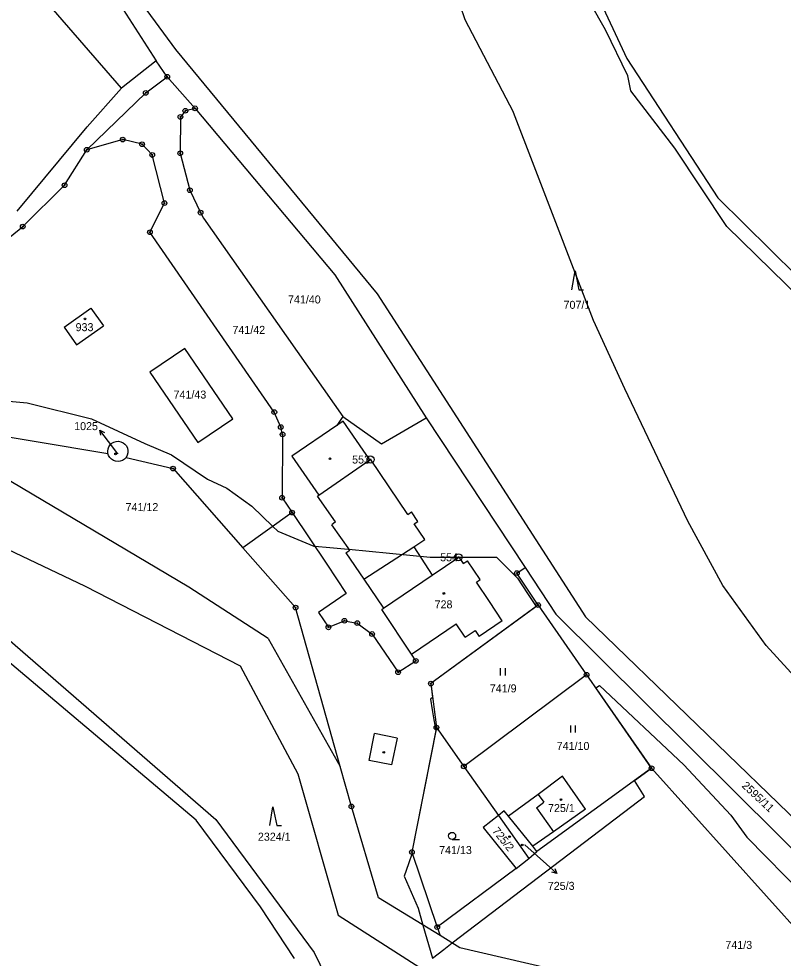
# Model space of a CAD drawing. Extents: x -439246 to -433691, y -1130252 to -1121148.
# Drawn here: x -437300.2 to -437137.8, y -1125272.6 to -1125073 of the extents above; entities that cross this region are included whole.
import ezdxf

# ---------------------------------------------------------------- set-up
doc = ezdxf.new("R2010")
doc.units = 0
for name, color, linetype in [('Vrstva 1', 7, 'Continuous'), ('Vrstva 16', 7, 'Continuous'), ('Vrstva 17', 7, 'Continuous'), ('Vrstva 18', 7, 'Continuous'), ('Vrstva 19', 7, 'Continuous'), ('Vrstva 24', 7, 'Continuous'), ('Vrstva 25', 7, 'Continuous'), ('Vrstva 3', 7, 'Continuous'), ('Vrstva 37', 7, 'Continuous'), ('Vrstva 4', 7, 'Continuous'), ('Vrstva 52', 7, 'Continuous')]:
    doc.layers.add(name, color=color, linetype=linetype)

msp = doc.modelspace()

# ---------------------------------------------------------------- linework, layer by layer
at = {"layer": 'Vrstva 1'}
msp.add_line((-437165.76, -1125232.24), (-437099.03, -1125306.63), dxfattribs=at)
for points in [[(-437184.04, -1125053.49), (-437171.05, -1125081.5)], [(-437281.89, -1125059.16), (-437266.94, -1125079.59)], [(-437278.39, -1125087.76), (-437299.88, -1125062.97)], [(-437278.09, -1125071.06), (-437271.03, -1125081.99)], [(-437266.94, -1125079.59), (-437224.08, -1125131.45)], [(-437271.03, -1125081.99), (-437278.39, -1125087.76)], [(-437268.7, -1125085.36), (-437271.03, -1125081.99)], [(-437171.05, -1125081.5), (-437151.7, -1125111.07)], [(-437273.27, -1125088.78), (-437268.7, -1125085.36)], [(-437268.7, -1125085.36), (-437262.78, -1125092.07)], [(-437285.69, -1125095.97), (-437278.39, -1125087.76)], [(-437285.79, -1125100.86), (-437273.27, -1125088.78)], [(-437262.78, -1125092.07), (-437264.85, -1125092.59)], [(-437262.78, -1125092.07), (-437233.06, -1125127.46)], [(-437265.9, -1125093.89), (-437265.93, -1125101.62)], [(-437264.85, -1125092.59), (-437265.9, -1125093.89)], [(-437300.58, -1125113.93), (-437285.69, -1125095.97)], [(-437278.16, -1125098.71), (-437285.79, -1125100.86)], [(-437274.03, -1125099.7), (-437278.16, -1125098.71)], [(-437271.88, -1125101.98), (-437274.03, -1125099.7)], [(-437290.5, -1125108.4), (-437285.79, -1125100.86)], [(-437269.28, -1125112.21), (-437271.88, -1125101.98)], [(-437265.93, -1125101.62), (-437263.88, -1125109.46)], [(-437299.41, -1125117.2), (-437290.5, -1125108.4)], [(-437263.88, -1125109.46), (-437261.62, -1125114.23)], [(-437272.37, -1125118.4), (-437269.28, -1125112.21)], [(-437151.7, -1125111.07), (-437118.1, -1125144.22)], [(-437261.62, -1125114.23), (-437261, -1125115.42)], [(-437261, -1125115.42), (-437231.4, -1125157.51)], [(-437325.27, -1125138.23), (-437299.41, -1125117.2)], [(-437245.94, -1125156.61), (-437272.37, -1125118.4)], [(-437233.06, -1125127.46), (-437213.7, -1125157.84)], [(-437224.08, -1125131.45), (-437179.84, -1125200.1)], [(-437290.63, -1125138.57), (-437284.92, -1125134.51)], [(-437284.92, -1125134.51), (-437282.26, -1125138.26)], [(-437290.63, -1125138.57), (-437287.96, -1125142.32)], [(-437287.96, -1125142.32), (-437282.26, -1125138.26)], [(-437264.97, -1125143.09), (-437272.43, -1125148.14)], [(-437254.73, -1125158.04), (-437264.97, -1125143.09)], [(-437272.43, -1125148.14), (-437262.19, -1125163.08)], [(-437329.19, -1125157.4), (-437281.29, -1125165.42)], [(-437262.19, -1125163.08), (-437254.73, -1125158.04)], [(-437244.57, -1125159.77), (-437245.94, -1125156.61)], [(-437231.4, -1125157.51), (-437232.69, -1125159.45)], [(-437231.4, -1125157.51), (-437223.14, -1125163.35)], [(-437223.14, -1125163.35), (-437213.7, -1125157.84)], [(-437213.7, -1125157.84), (-437192.64, -1125189.64)], [(-437244.18, -1125161.34), (-437244.57, -1125159.77)], [(-437232.69, -1125159.45), (-437242.19, -1125165.97), (-437236.46, -1125174.27)], [(-437244.18, -1125161.34), (-437244.3, -1125174.79)], [(-437281.27, -1125164.43), (-437281.1, -1125163.96)], [(-437281.1, -1125163.96), (-437280.82, -1125163.54)], [(-437280.82, -1125163.54), (-437280.45, -1125163.21)], [(-437280.45, -1125163.21), (-437280.02, -1125162.96)], [(-437280.02, -1125162.96), (-437279.53, -1125162.83)], [(-437279.53, -1125162.83), (-437279.03, -1125162.8)], [(-437279.03, -1125162.8), (-437278.54, -1125162.9)], [(-437278.54, -1125162.9), (-437278.09, -1125163.1)], [(-437278.09, -1125163.1), (-437277.69, -1125163.4)], [(-437277.69, -1125163.4), (-437277.38, -1125163.79)], [(-437277.38, -1125163.79), (-437277.16, -1125164.24)], [(-437281.35, -1125164.92), (-437281.27, -1125164.43)], [(-437281.29, -1125165.42), (-437281.35, -1125164.92)], [(-437281.16, -1125165.82), (-437281.29, -1125165.42)], [(-437280.9, -1125166.24), (-437281.16, -1125165.82)], [(-437277.18, -1125165.72), (-437277.44, -1125166.21)], [(-437277.06, -1125165.23), (-437277.18, -1125165.72)], [(-437277.16, -1125164.24), (-437277.04, -1125164.73)], [(-437277.04, -1125164.73), (-437277.06, -1125165.23)], [(-437280.56, -1125166.61), (-437280.9, -1125166.24)], [(-437280.13, -1125166.88), (-437280.56, -1125166.61)], [(-437279.66, -1125167.04), (-437280.13, -1125166.88)], [(-437279.16, -1125167.09), (-437279.66, -1125167.04)], [(-437278.67, -1125167.03), (-437279.16, -1125167.09)], [(-437278.2, -1125166.85), (-437278.67, -1125167.03)], [(-437277.78, -1125166.57), (-437278.2, -1125166.85)], [(-437277.44, -1125166.21), (-437277.78, -1125166.57)], [(-437277.44, -1125166.21), (-437267.47, -1125168.61)], [(-437267.47, -1125168.61), (-437252.65, -1125185.42)], [(-437264.1, -1125193.82), (-437301.92, -1125171.31)], [(-437244.3, -1125174.79), (-437242.17, -1125177.95)], [(-437236.76, -1125174.48), (-437236.46, -1125174.27)], [(-437232.96, -1125179.93), (-437236.76, -1125174.48)], [(-437242.17, -1125177.95), (-437252.65, -1125185.42)], [(-437242.17, -1125177.95), (-437234.78, -1125188.87)], [(-437232.96, -1125179.93), (-437233.72, -1125180.52)], [(-437229.93, -1125185.96), (-437233.72, -1125180.52)], [(-437310.14, -1125182.17), (-437286.12, -1125193.55)], [(-437252.65, -1125185.42), (-437241.43, -1125198.13)], [(-437230.72, -1125186.51), (-437229.93, -1125185.96)], [(-437230.72, -1125186.51), (-437226.92, -1125192.08)], [(-437234.78, -1125188.87), (-437230.7, -1125195.16)], [(-437194.39, -1125190.8), (-437192.64, -1125189.64)], [(-437192.64, -1125189.64), (-437186.11, -1125199.49)], [(-437189.89, -1125197.6), (-437194.39, -1125190.8)], [(-437286.12, -1125193.55), (-437253.22, -1125210.53)], [(-437247.25, -1125204.7), (-437264.1, -1125193.82)], [(-437226.92, -1125192.08), (-437222.72, -1125198.23)], [(-437230.7, -1125195.16), (-437236.52, -1125199.18)], [(-437311.33, -1125197.2), (-437258.37, -1125243.11)], [(-437189.89, -1125197.6), (-437212.67, -1125214.28)], [(-437189.89, -1125197.6), (-437179.59, -1125212.39)], [(-437262.54, -1125243.26), (-437315.87, -1125198.3)], [(-437231.95, -1125231.89), (-437241.43, -1125198.13)], [(-437236.52, -1125199.18), (-437234.43, -1125202.32)], [(-437223.12, -1125198.5), (-437222.72, -1125198.23)], [(-437216.77, -1125208), (-437223.12, -1125198.5)], [(-437119.82, -1125265.32), (-437186.11, -1125199.49)], [(-437234.43, -1125202.32), (-437231.04, -1125200.93)], [(-437231.04, -1125200.93), (-437228.31, -1125201.43)], [(-437228.31, -1125201.43), (-437225.15, -1125203.74)], [(-437179.84, -1125200.1), (-437132.38, -1125246)], [(-437225.15, -1125203.74), (-437219.64, -1125211.87)], [(-437247.25, -1125204.7), (-437231.95, -1125231.89)], [(-437215.89, -1125209.44), (-437216.77, -1125208)], [(-437219.64, -1125211.87), (-437215.89, -1125209.44)], [(-437253.22, -1125210.53), (-437240.96, -1125233.42)], [(-437179.59, -1125212.39), (-437205.67, -1125231.86)], [(-437179.59, -1125212.39), (-437165.76, -1125232.24)], [(-437212.67, -1125214.28), (-437211.5, -1125223.61)], [(-437211.5, -1125223.61), (-437216.7, -1125250.05)], [(-437211.5, -1125223.61), (-437205.67, -1125231.86)], [(-437229.57, -1125240.37), (-437231.95, -1125231.89)], [(-437205.67, -1125231.86), (-437198.32, -1125242.27)], [(-437240.96, -1125233.42), (-437232.4, -1125263.46)], [(-437165.76, -1125232.24), (-437190.17, -1125249.92)], [(-437184.68, -1125233.96), (-437189.9, -1125237.8)], [(-437179.78, -1125240.92), (-437184.68, -1125233.96)], [(-437189.9, -1125237.8), (-437196.18, -1125242.41)], [(-437223.78, -1125259.79), (-437229.57, -1125240.37)], [(-437197.08, -1125241.29), (-437198.32, -1125242.27)], [(-437196.18, -1125242.41), (-437197.08, -1125241.29)], [(-437179.78, -1125240.92), (-437186.65, -1125245.76)], [(-437248.91, -1125261.69), (-437262.54, -1125243.26)], [(-437258.37, -1125243.11), (-437237.5, -1125271.39)], [(-437198.32, -1125242.27), (-437201.54, -1125244.81)], [(-437198.32, -1125242.27), (-437191.85, -1125251.43)], [(-437191.04, -1125248.84), (-437196.18, -1125242.41)], [(-437201.54, -1125244.81), (-437194.58, -1125253.52)], [(-437186.65, -1125245.76), (-437191.04, -1125248.84)], [(-437191.85, -1125251.43), (-437190.17, -1125249.92)], [(-437190.17, -1125249.92), (-437191.04, -1125248.84)], [(-437216.7, -1125250.05), (-437211.32, -1125266.01)], [(-437194.58, -1125253.52), (-437191.85, -1125251.43)], [(-437194.58, -1125253.52), (-437211.32, -1125266.01)], [(-437210.71, -1125267.81), (-437223.78, -1125259.79)], [(-437241.63, -1125272.65), (-437248.91, -1125261.69)], [(-437232.4, -1125263.46), (-437207.69, -1125279.24)], [(-437211.32, -1125266.01), (-437210.71, -1125267.81)], [(-437206.51, -1125270.39), (-437210.71, -1125267.81)], [(-437237.5, -1125271.39), (-437232.62, -1125281.42)], [(-437169.29, -1125279.04), (-437206.51, -1125270.39)]]:
    msp.add_lwpolyline(points, dxfattribs=at)
at = {"layer": 'Vrstva 16'}
for p, q in [((-437281.19, -1125162.82), (-437283, -1125160.43)), ((-437188.13, -1125252.6), (-437185.88, -1125254.59))]:
    msp.add_line(p, q, dxfattribs=at)
for points in [[(-437282.8, -1125161.53), (-437283, -1125160.43), (-437282, -1125160.92)], [(-437279.18, -1125165.47), (-437281.19, -1125162.82)], [(-437192.7, -1125248.56), (-437188.13, -1125252.6)], [(-437186.3, -1125253.55), (-437185.88, -1125254.59), (-437186.96, -1125254.3)]]:
    msp.add_lwpolyline(points, dxfattribs=at)
at = {"layer": 'Vrstva 24'}
for centre, radius in [((-437268.7, -1125085.36), 0.5), ((-437268.7, -1125085.36), 0.1), ((-437273.27, -1125088.78), 0.5), ((-437273.27, -1125088.78), 0.1), ((-437264.85, -1125092.59), 0.5), ((-437262.78, -1125092.07), 0.5), ((-437262.78, -1125092.07), 0.1), ((-437265.9, -1125093.89), 0.5), ((-437265.9, -1125093.89), 0.1), ((-437264.85, -1125092.59), 0.1), ((-437278.16, -1125098.71), 0.5), ((-437278.16, -1125098.71), 0.1), ((-437274.03, -1125099.7), 0.5), ((-437274.03, -1125099.7), 0.1), ((-437285.79, -1125100.86), 0.5), ((-437285.79, -1125100.86), 0.1), ((-437271.88, -1125101.98), 0.5), ((-437271.88, -1125101.98), 0.1), ((-437265.93, -1125101.62), 0.5), ((-437265.93, -1125101.62), 0.1), ((-437290.5, -1125108.4), 0.5), ((-437290.5, -1125108.4), 0.1), ((-437263.88, -1125109.46), 0.5), ((-437263.88, -1125109.46), 0.1), ((-437269.28, -1125112.21), 0.5), ((-437269.28, -1125112.21), 0.1), ((-437261.62, -1125114.23), 0.5), ((-437261.62, -1125114.23), 0.1), ((-437299.41, -1125117.2), 0.5), ((-437299.41, -1125117.2), 0.1), ((-437272.37, -1125118.4), 0.5), ((-437272.37, -1125118.4), 0.1), ((-437245.94, -1125156.61), 0.5), ((-437245.94, -1125156.61), 0.1), ((-437244.57, -1125159.77), 0.5), ((-437244.57, -1125159.77), 0.1), ((-437244.18, -1125161.34), 0.5), ((-437244.18, -1125161.34), 0.1), ((-437225.49, -1125166.67), 0.75), ((-437267.47, -1125168.61), 0.5), ((-437225.49, -1125166.67), 0.1), ((-437267.47, -1125168.61), 0.1), ((-437244.3, -1125174.79), 0.5), ((-437244.3, -1125174.79), 0.1), ((-437242.17, -1125177.95), 0.5), ((-437242.17, -1125177.95), 0.1), ((-437206.78, -1125187.44), 0.75), ((-437206.78, -1125187.44), 0.1), ((-437194.39, -1125190.8), 0.5), ((-437194.39, -1125190.8), 0.1), ((-437241.43, -1125198.13), 0.5), ((-437241.43, -1125198.13), 0.1), ((-437189.89, -1125197.6), 0.5), ((-437189.89, -1125197.6), 0.1), ((-437234.43, -1125202.32), 0.5), ((-437231.04, -1125200.93), 0.5), ((-437231.04, -1125200.93), 0.1), ((-437228.31, -1125201.43), 0.5), ((-437228.31, -1125201.43), 0.1), ((-437234.43, -1125202.32), 0.1), ((-437225.15, -1125203.74), 0.5), ((-437225.15, -1125203.74), 0.1), ((-437215.89, -1125209.44), 0.5), ((-437215.89, -1125209.44), 0.1), ((-437219.64, -1125211.87), 0.5), ((-437219.64, -1125211.87), 0.1), ((-437179.59, -1125212.39), 0.5), ((-437212.67, -1125214.28), 0.5), ((-437179.59, -1125212.39), 0.1), ((-437212.67, -1125214.28), 0.1), ((-437211.5, -1125223.61), 0.5), ((-437211.5, -1125223.61), 0.1), ((-437205.67, -1125231.86), 0.5), ((-437205.67, -1125231.86), 0.1), ((-437165.76, -1125232.24), 0.5), ((-437165.76, -1125232.24), 0.1), ((-437229.57, -1125240.37), 0.5), ((-437229.57, -1125240.37), 0.1), ((-437216.7, -1125250.05), 0.5), ((-437216.7, -1125250.05), 0.1), ((-437211.32, -1125266.01), 0.5), ((-437211.32, -1125266.01), 0.1)]:
    msp.add_circle(centre, radius, dxfattribs=at)
at = {"layer": 'Vrstva 25'}
for p, q in [((-437197.85, -1125212.52), (-437197.85, -1125211.02)), ((-437196.85, -1125212.52), (-437196.85, -1125211.02)), ((-437182.94, -1125224.67), (-437182.94, -1125223.17)), ((-437181.94, -1125224.67), (-437181.94, -1125223.17)), ((-437208.16, -1125247.38), (-437206.56, -1125247.38))]:
    msp.add_line(p, q, dxfattribs=at)
for points in [[(-437182.71, -1125130.62), (-437182.01, -1125126.62), (-437181.21, -1125130.62), (-437180.21, -1125130.62)], [(-437246.93, -1125244.45), (-437246.23, -1125240.45), (-437245.43, -1125244.45), (-437244.43, -1125244.45)]]:
    msp.add_lwpolyline(points, dxfattribs=at)
for centre, radius in [((-437286.19, -1125136.8), 0.175), ((-437279.68, -1125165.47), 0.175), ((-437234.12, -1125166.51), 0.175), ((-437209.91, -1125195.12), 0.175), ((-437222.68, -1125228.89), 0.175), ((-437185.01, -1125238.9), 0.175), ((-437208.16, -1125246.63), 0.75), ((-437195.96, -1125246.79), 0.175), ((-437193.27, -1125248.56), 0.175)]:
    msp.add_circle(centre, radius, dxfattribs=at)
at = {"layer": 'Vrstva 3'}
for points in [[(-437290.63, -1125138.57), (-437284.92, -1125134.51)], [(-437284.92, -1125134.51), (-437282.26, -1125138.26)], [(-437290.63, -1125138.57), (-437287.96, -1125142.32)], [(-437287.96, -1125142.32), (-437282.26, -1125138.26)], [(-437281.27, -1125164.43), (-437281.1, -1125163.96)], [(-437281.1, -1125163.96), (-437280.82, -1125163.54)], [(-437280.82, -1125163.54), (-437280.45, -1125163.21)], [(-437280.45, -1125163.21), (-437280.02, -1125162.96)], [(-437280.02, -1125162.96), (-437279.53, -1125162.83)], [(-437279.53, -1125162.83), (-437279.03, -1125162.8)], [(-437279.03, -1125162.8), (-437278.54, -1125162.9)], [(-437278.54, -1125162.9), (-437278.09, -1125163.1)], [(-437278.09, -1125163.1), (-437277.69, -1125163.4)], [(-437277.69, -1125163.4), (-437277.38, -1125163.79)], [(-437277.38, -1125163.79), (-437277.16, -1125164.24)], [(-437281.35, -1125164.92), (-437281.27, -1125164.43)], [(-437281.29, -1125165.42), (-437281.35, -1125164.92)], [(-437281.16, -1125165.82), (-437281.29, -1125165.42)], [(-437280.9, -1125166.24), (-437281.16, -1125165.82)], [(-437277.18, -1125165.72), (-437277.44, -1125166.21)], [(-437277.06, -1125165.23), (-437277.18, -1125165.72)], [(-437277.16, -1125164.24), (-437277.04, -1125164.73)], [(-437277.04, -1125164.73), (-437277.06, -1125165.23)], [(-437280.56, -1125166.61), (-437280.9, -1125166.24)], [(-437280.13, -1125166.88), (-437280.56, -1125166.61)], [(-437279.66, -1125167.04), (-437280.13, -1125166.88)], [(-437279.16, -1125167.09), (-437279.66, -1125167.04)], [(-437278.67, -1125167.03), (-437279.16, -1125167.09)], [(-437278.2, -1125166.85), (-437278.67, -1125167.03)], [(-437277.78, -1125166.57), (-437278.2, -1125166.85)], [(-437277.44, -1125166.21), (-437277.78, -1125166.57)], [(-437212.37, -1125191.21), (-437206.74, -1125187.39)], [(-437206.74, -1125187.39), (-437205.79, -1125188.79)], [(-437205.79, -1125188.79), (-437204.86, -1125188.17)], [(-437202.18, -1125192.16), (-437204.86, -1125188.17)], [(-437222.72, -1125198.23), (-437212.37, -1125191.21)], [(-437203.01, -1125192.71), (-437202.18, -1125192.16)], [(-437200.25, -1125196.82), (-437203.01, -1125192.71)], [(-437197.49, -1125200.93), (-437200.25, -1125196.82)], [(-437223.12, -1125198.5), (-437222.72, -1125198.23)], [(-437216.77, -1125208), (-437223.12, -1125198.5)], [(-437216.77, -1125208), (-437207.29, -1125201.55)], [(-437205.36, -1125204.42), (-437207.29, -1125201.55)], [(-437197.49, -1125200.93), (-437202.42, -1125204.25)], [(-437205.36, -1125204.42), (-437203.26, -1125203)], [(-437203.26, -1125203), (-437202.42, -1125204.25)], [(-437184.68, -1125233.96), (-437189.9, -1125237.8)], [(-437179.78, -1125240.92), (-437184.68, -1125233.96)], [(-437189.9, -1125237.8), (-437188.66, -1125239.49)], [(-437190.24, -1125240.66), (-437188.66, -1125239.49)], [(-437197.08, -1125241.29), (-437198.32, -1125242.27)], [(-437196.18, -1125242.41), (-437197.08, -1125241.29)], [(-437190.24, -1125240.66), (-437186.65, -1125245.76)], [(-437179.78, -1125240.92), (-437186.65, -1125245.76)], [(-437198.32, -1125242.27), (-437201.54, -1125244.81)], [(-437191.04, -1125248.84), (-437196.18, -1125242.41)], [(-437201.54, -1125244.81), (-437194.58, -1125253.52)], [(-437191.85, -1125251.43), (-437190.17, -1125249.92)], [(-437190.17, -1125249.92), (-437191.04, -1125248.84)], [(-437194.58, -1125253.52), (-437191.85, -1125251.43)]]:
    msp.add_lwpolyline(points, dxfattribs=at)
at = {"layer": 'Vrstva 37'}
for centre in [(-437286.19, -1125136.8), (-437279.68, -1125165.47), (-437209.91, -1125195.12), (-437185.01, -1125238.9), (-437195.96, -1125246.79)]:
    msp.add_circle(centre, 0.175, dxfattribs=at)
at = {"layer": 'Vrstva 4'}
for points in [[(-437225.63, -1125166.72), (-437231.33, -1125158.52), (-437232.69, -1125159.45)], [(-437236.46, -1125174.27), (-437225.63, -1125166.72)], [(-437225.63, -1125166.72), (-437225.51, -1125166.63)], [(-437217.6, -1125178.33), (-437225.51, -1125166.63)], [(-437217.6, -1125178.33), (-437216.82, -1125177.79)], [(-437215.43, -1125179.81), (-437216.82, -1125177.79)], [(-437216.21, -1125180.35), (-437215.43, -1125179.81)], [(-437213.94, -1125183.64), (-437216.21, -1125180.35)], [(-437216.26, -1125185.24), (-437213.94, -1125183.64)], [(-437226.92, -1125192.08), (-437216.26, -1125185.24)], [(-437216.26, -1125185.24), (-437212.37, -1125191.21)], [(-437212.37, -1125191.21), (-437206.74, -1125187.39)], [(-437206.74, -1125187.39), (-437205.79, -1125188.79)], [(-437205.79, -1125188.79), (-437204.86, -1125188.17)], [(-437202.18, -1125192.16), (-437204.86, -1125188.17)], [(-437222.72, -1125198.23), (-437212.37, -1125191.21)], [(-437203.01, -1125192.71), (-437202.18, -1125192.16)], [(-437200.25, -1125196.82), (-437203.01, -1125192.71)], [(-437197.49, -1125200.93), (-437200.25, -1125196.82)], [(-437216.77, -1125208), (-437207.29, -1125201.55)], [(-437205.36, -1125204.42), (-437207.29, -1125201.55)], [(-437197.49, -1125200.93), (-437202.42, -1125204.25)], [(-437205.36, -1125204.42), (-437203.26, -1125203)], [(-437203.26, -1125203), (-437202.42, -1125204.25)], [(-437225.78, -1125230.58), (-437224.62, -1125224.9)], [(-437219.85, -1125225.88), (-437224.62, -1125224.9)], [(-437219.85, -1125225.88), (-437221.02, -1125231.56)], [(-437221.02, -1125231.56), (-437225.78, -1125230.58)], [(-437189.9, -1125237.8), (-437188.66, -1125239.49)], [(-437190.24, -1125240.66), (-437188.66, -1125239.49)], [(-437190.24, -1125240.66), (-437186.65, -1125245.76)]]:
    msp.add_lwpolyline(points, dxfattribs=at)
at = {"layer": 'Vrstva 52'}
for points in [[(-437134.64, -1125213.64), (-437141.45, -1125206.19), (-437150.61, -1125193.4), (-437158.07, -1125179.77), (-437171.49, -1125151.65), (-437178.09, -1125137.16), (-437190.71, -1125104.35), (-437195.11, -1125092.94), (-437195.14, -1125092.85), (-437205.36, -1125073.26), (-437211.75, -1125054.51)], [(-437124.68, -1125141.69), (-437149.76, -1125117.14), (-437160.84, -1125100.52), (-437170.21, -1125088.38), (-437170.85, -1125085.19), (-437175.54, -1125075.39), (-437181.93, -1125064.1)], [(-437303.14, -1125154.21), (-437298.45, -1125154.63), (-437284.82, -1125158.04), (-437273.46, -1125163.28), (-437267.78, -1125165.71), (-437260.11, -1125170.82), (-437256.06, -1125172.74), (-437250.74, -1125176.57), (-437246.27, -1125180.87), (-437245.2, -1125181.9), (-437237.53, -1125185.1), (-437237.41, -1125185.11), (-437237.32, -1125185.11), (-437234.16, -1125185.38), (-437230.26, -1125185.71), (-437230.15, -1125185.72), (-437230.09, -1125185.72), (-437212.82, -1125187.44)], [(-437212.82, -1125187.44), (-437198.76, -1125187.44), (-437194.28, -1125191.91), (-437192.14, -1125195.14), (-437190.3, -1125197.9), (-437212.67, -1125214.28), (-437212.3, -1125217.24), (-437212.78, -1125217.57), (-437212.39, -1125219.82), (-437212.02, -1125221.98), (-437211.63, -1125224.26), (-437216.7, -1125250.05), (-437216.62, -1125250.26), (-437217.44, -1125252.57), (-437218.36, -1125255.18), (-437215.37, -1125262), (-437214.35, -1125265.58), (-437212.35, -1125272.57), (-437209.93, -1125270.73), (-437208.16, -1125269.37), (-437168.51, -1125239.2), (-437167.29, -1125238.28), (-437169.43, -1125234.89), (-437165.76, -1125232.24), (-437177.64, -1125215.19), (-437176.82, -1125214.71), (-437158.92, -1125231.54), (-437148.91, -1125242.19), (-437145.5, -1125246.87), (-437121, -1125271.8)]]:
    msp.add_lwpolyline(points, dxfattribs=at)

# ---------------------------------------------------------------- texts
at = {"layer": 'Vrstva 16'}
for s, p in [('1025', (-437288.48, -1125160.43)), ('725/3', (-437187.83, -1125258.09))]:
    msp.add_text(s, height=1.7, dxfattribs=at).set_placement(p)
at = {"layer": 'Vrstva 17'}
for s, p in [('553', (-437229.41, -1125167.52)), ('554', (-437210.71, -1125188.29))]:
    msp.add_text(s, height=1.7, dxfattribs=at).set_placement(p)
at = {"layer": 'Vrstva 18'}
for s, p in [('741/40', (-437243.04, -1125133.52)), ('707/1', (-437184.48, -1125134.66)), ('741/42', (-437254.84, -1125139.98)), ('741/43', (-437267.36, -1125153.73)), ('741/12', (-437277.55, -1125177.63)), ('741/9', (-437200.15, -1125216.14)), ('741/10', (-437185.94, -1125228.37)), ('2324/1', (-437249.43, -1125247.65)), ('741/13', (-437210.92, -1125250.48)), ('741/3', (-437150.09, -1125270.64))]:
    msp.add_text(s, height=1.7, dxfattribs=at).set_placement(p)
msp.add_text('2595/11', height=1.7, rotation=316.997, dxfattribs=at).set_placement((-437146.73, -1125236.13))
at = {"layer": 'Vrstva 19'}
for s, height, p in [('933', 1.7, (-437288.17, -1125139.41)), ('1025', 0.1, (-437279.32, -1125165.47)), ('728', 1.7, (-437211.88, -1125198.29)), ('725/1', 1.7, (-437187.78, -1125241.56)), ('725/3', 0.1, (-437192.89, -1125248.56))]:
    msp.add_text(s, height=height, dxfattribs=at).set_placement(p)
msp.add_text('725/2', height=1.7, rotation=308.4286, dxfattribs=at).set_placement((-437199.72, -1125245.61))

doc.saveas('drawing.dxf')
